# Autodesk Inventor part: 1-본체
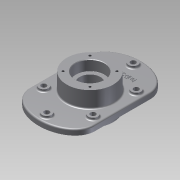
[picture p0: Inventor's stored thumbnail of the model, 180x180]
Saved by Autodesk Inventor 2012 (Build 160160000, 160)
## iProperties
Created: 2015-02
Part Number: 1-본체
Material: Default
Document SubType Name: Modeling
Designer: Administrator
Density: 1 g/cm^3
Author: Administrator
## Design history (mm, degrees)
sketch "스케치1"
  geometry: L1 (-70, -60)-(-70, 0); L2 (70, -60)-(70, 0); L3 (-70, 60)-(-70, 0); L4 (70, 60)-(70, 0); 3 further points; 2 other entities
  constraints: 8 end point, 3 vertical, 1 parallel, 8 other
extrude "돌출1" new body sketch "스케치1" distance "d4" = 12; taper "d5" = 0 deg
node "작업 평면1"
sketch "스케치11"
  geometry: L1 (-70, -60)-(-70, 60) reference; L2 (-70, 60)-(-70, 46.5); L3 (-70, 46.5)-(-53, 46.5); L4 (-70, -60)-(-70, -46.5); C1 r 10 at (-53, 46.5); C2 r 10 at (-53, -46.5); C3 r 10 at (0, 93); C4 r 10 at (53, 46.5); C5 r 10 at (53, -46.5); C6 r 10 at (0, -93); 1 further point
  constraints: 6 centre point, 6 end point, 2 point on line, 1 coincident
  dimensions: "d49" = 20 diameter of C1; "d51" = 20 diameter of C3; "d52" = 20 diameter of C4; "d54" = 20 diameter of C6
extrude "돌출8" join sketch "스케치11" distance "d55" = 5; taper "d56" = 0 deg
node "작업 평면2"
sketch "스케치12"
  geometry: C1 r 50 at (0, 0); 1 further point
  constraints: 1 centre point, 1 coincident
  dimensions: "d58" = 100 diameter of C1
extrude "돌출9" join sketch "스케치12" distance "d59" = 70; taper "d60" = 0 deg
sketch "스케치13"
  geometry: C1 r 50 at (0, 0) reference; C2 r 31 at (0, 0)
  constraints: 1 centre point, 1 coincident
  dimensions: "d61" = 62 diameter of C2
extrude "돌출10" cut sketch "스케치13" distance "d62" = 22; taper "d63" = 0 deg
sketch "스케치14"
  geometry: C1 r 50 at (0, 0) reference; C2 r 31 at (0, 0)
  constraints: 1 centre point, 1 coincident
  dimensions: "d64" = 62 diameter of C2
extrude "돌출11" cut sketch "스케치14" distance "d65" = 22; taper "d66" = 0 deg
sketch "스케치15"
  geometry: C1 r 31 at (0, 0) reference; C2 r 22.5 at (0, 0)
  constraints: 1 centre point, 1 coincident
  dimensions: "d67" = 45 diameter of C2
extrude "돌출12" cut sketch "스케치15" stored distance "d68" = 22; taper "d69" = 0 deg
sketch "스케치16"
  geometry: C1 r 10 at (0, 0) reference; C2 r 10 at (-53, -46.5) reference; C3 r 10 at (53, -46.5) reference; C4 r 10 at (53, -139.5) reference; C5 r 10 at (0, -186) reference; C6 r 10 at (-53, -139.5) reference; C7 r 5.5 at (0, 0); C8 r 5.5 at (53, -46.5); C9 r 5.5 at (-53, -46.5); C10 r 5.5 at (-53, -139.5); C11 r 5.5 at (53, -139.5); C12 r 5.5 at (0, -186); 1 further point
  constraints: 6 centre point, 1 coincident
extrude "돌출13" cut sketch "스케치16" stored distance "d71" = 22; taper "d72" = 0 deg
sketch "스케치17"
  geometry: L1 (0, 0)-(-58.647, 0); C1 r 50 at (0, 0) reference; 1 further point
  constraints: 2 end point, 1 horizontal
hole "구멍1" sketch "스케치17" at (-28.991, 28.991) diameter "d75" = 4.917; stored, may be unused: countersink angle "d79" = 90 deg, drill point angle "d81" = 118 deg; dims "d76" = 10, "d77" = 4, "d78" = 2, "d80" = 13
sketch "스케치18"
  geometry: 1 further point
hole "구멍2" sketch "스케치18" at (-28.991, 28.991) diameter "d87" = 4.917; stored, may be unused: countersink angle "d91" = 90 deg, drill point angle "d93" = 118 deg; dims "d88" = 10, "d89" = 4, "d90" = 2, "d92" = 13
fillet "모깎기1" dims "d97" = 3, "d98" = 0.3
sketch "스케치19"
  geometry: 1 further point
  constraints: 1 other
feature "엠보싱1" sketch "스케치19" dims "d100" = 1, "d101" = 0
chamfer "모따기1" distance "d102" = 1; stored, may be unused: second distance "d103" = 2, angle "d104" = 45 deg
node "솔리드1"
pattern_circular "원형 패턴1" dims angle "d83" = 360 deg
pattern_circular "원형 패턴2" dims angle "d95" = 360 deg
node "투영된 루프6"
node "투영된 루프7"
node "투영된 루프8"
node "투영된 루프9"
node "투영된 루프10"
other parameters: "d6" = -23, "d57" = -23
